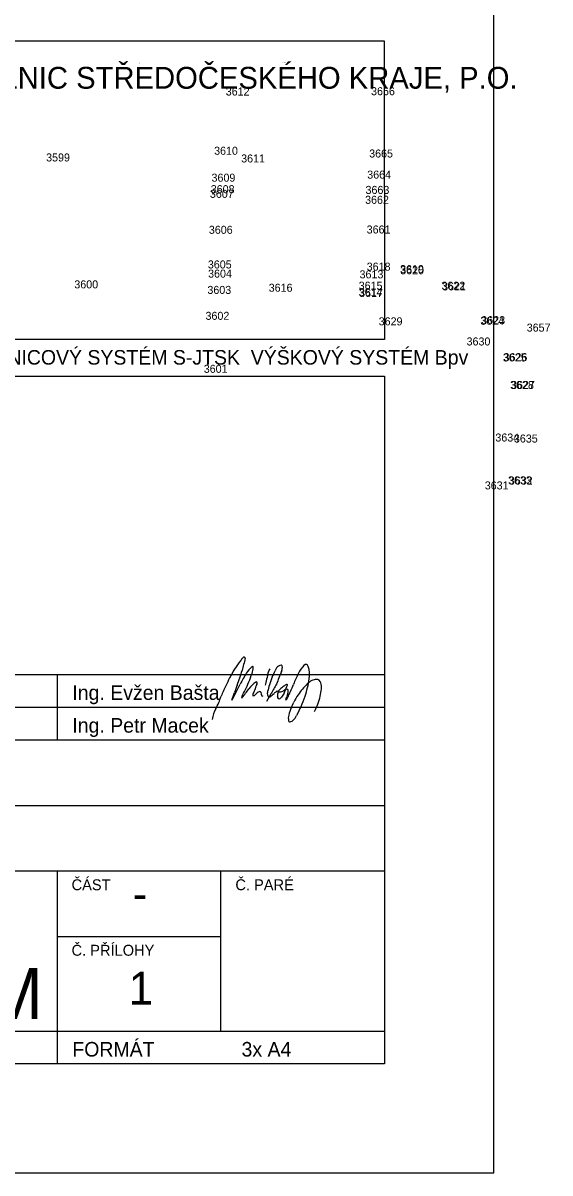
# Model space of a CAD drawing. Extents: x -740053 to -737517, y -1033516 to -1032476.
# Drawn here: x -739026.2 to -738990, y -1032630.6 to -1032551.6 of the extents above; entities that cross this region are included whole.
import ezdxf

# ---------------------------------------------------------------- set-up
doc = ezdxf.new("R2010")
doc.units = 0
for name, color, linetype in [('_MIKA', 7, 'Continuous'), ('bod-cislo', 7, 'Continuous'), ('bod-oznac', 7, 'Continuous'), ('bod-vyska100', 7, 'Continuous'), ('promika-formát', 7, 'Continuous'), ('promika-rozp', 7, 'Continuous'), ('promika-rozp-text-firmy', 7, 'Continuous')]:
    doc.layers.add(name, color=color, linetype=linetype)

# ---------------------------------------------------------------- blocks, each defined once
blk = doc.blocks.new('POINT_DISPLAY')
blk.add_line((0, 0), (0, 0))

msp = doc.modelspace()

# ---------------------------------------------------------------- linework, layer by layer
at = {"layer": '_MIKA'}
msp.add_lwpolyline([(-739009.476, -1032598.222), (-739009.188, -1032597.697)], dxfattribs=at)
for centre, radius, start, end in [((-739005.594, -1032599.849), 7.198, 142.23523, 153.41785), ((-738992.887, -1032609.693), 23.272, 141.62525, 142.23523), ((-738996.81, -1032599.261), 14.699, 164.31686, 167.58851), ((-739011.038, -1032595.32), 0.119, 77.65258, 141.62525), ((-739011.027, -1032595.27), 0.068, 344.31686, 77.65258), ((-739053.316, -1032582.132), 44.406, 340.28609, 341.66347), ((-739005.179, -1032599.978), 6.785, 146.97351, 154.45028), ((-739020.269, -1032592.912), 10.355, 333.90134, 340.8079), ((-739009.171, -1032597.384), 2.025, 132.28695, 146.97351), ((-739010.453, -1032595.953), 0.104, 95.68301, 139.83775), ((-739011.889, -1032595.826), 1.483, 340.68391, 357.12395), ((-739010.452, -1032595.892), 0.0444, 349.81416, 105.49835), ((-739010.138, -1032596.167), 0.767, 337.07897, 353.18058), ((-739008.911, -1032596.313), 0.468, 139.22083, 173.18058), ((-739013.245, -1032594.388), 4.673, 332.41674, 338.14258), ((-739008.101, -1032596.451), 0.869, 143.70851, 158.14258), ((-738853.15, -1032658.556), 167.377, 158.12382, 158.43787), ((-739008.419, -1032596.217), 0.474, 99.82381, 143.70851), ((-739008.537, -1032595.875), 0.13, 357.13165, 73.63723), ((-739009.365, -1032595.834), 0.96, 338.12382, 357.13165), ((-739001.446, -1032599.381), 6.616, 152.29875, 159.50378), ((-739004.761, -1032597.641), 2.872, 139.05622, 152.29875), ((-739006.8, -1032595.872), 0.173, 15.21404, 139.05622), ((-739008.446, -1032596.403), 1.902, 351.39073, 17.62988), ((-738926.054, -1032639.648), 96.139, 153.41785, 153.77616), ((-739027.937, -1032589.099), 18.439, 330.61841, 334.45028), ((-738990.516, -1032604.635), 22.304, 160.28609, 161.69166), ((-739009.162, -1032598.454), 1.885, 124.89597, 145.05699), ((-739004.859, -1032599.225), 5.731, 157.76834, 162.23546), ((-739010.196, -1032596.972), 0.0779, 55.10403, 124.89597), ((-739010.395, -1032596.962), 0.25, 337.76834, 12.42518), ((-739006.502, -1032597.698), 3.146, 165.90811, 169.54357), ((-738990.1, -1032601.816), 20.058, 164.53011, 165.90811), ((-738995.104, -1032601.534), 14.867, 162.64406, 164.43328), ((-739000.908, -1032599.72), 8.786, 158.86527, 162.64406), ((-738990.399, -1032608.008), 21.433, 149.22929, 151.24035), ((-739007.055, -1032598.93), 2.144, 119.74147, 125.81479), ((-739008.098, -1032597.105), 0.0415, 339.1031, 119.74147), ((-739013.783, -1032594.934), 6.128, 338.12374, 339.1031), ((-739014.076, -1032594.66), 6.867, 335.01458, 339.50378), ((-739002.155, -1032601.506), 6.376, 135.47239, 144.29948), ((-739014.179, -1032595.535), 7.701, 342.2433, 351.39073), ((-739005.897, -1032597.826), 1.128, 115.27288, 135.47239), ((-739006.032, -1032597.54), 0.811, 93.24087, 115.27288), ((-739006.06, -1032597.039), 0.309, 16.61177, 93.24087), ((-739006.748, -1032597.244), 1.026, 352.45357, 16.61177), ((-739021.984, -1032594.371), 10.012, 334.10342, 339.46538), ((-739005.242, -1032600.642), 7.866, 153.77616, 159.46538), ((-739032.867, -1032590.622), 22.304, 340.28609, 341.69166), ((-739010.943, -1032597.989), 0.266, 150.33743, 175.43081), ((-739016.415, -1032594.872), 6.032, 330.33743, 334.51836), ((-739018.32, -1032592.055), 9.287, 320.38725, 325.05699), ((-739010.303, -1032597.777), 0.143, 157.34282, 210.29061), ((-739008.128, -1032598.685), 2.501, 151.08165, 157.34281), ((-739010.446, -1032597.584), 0.266, 274.06523, 322.04071), ((-739009.824, -1032598.069), 0.522, 109.96924, 142.04071), ((-739009.953, -1032597.661), 0.0966, 16.46783, 120.57707), ((-739011.327, -1032597.902), 1.491, 4.64701, 10.37671), ((-739009.75, -1032597.783), 0.0917, 178.87234, 265.72159), ((-739008.94, -1032597.679), 0.503, 164.43328, 200.27708), ((-739009.305, -1032597.814), 0.115, 200.27708, 295.62005), ((-739010.747, -1032595.807), 2.584, 305.25171, 313.28111), ((-739008.17, -1032598.543), 1.174, 123.9927, 133.28111), ((-739008.769, -1032597.617), 0.0751, 330.79764, 140.06184), ((-739008.568, -1032597.918), 0.174, 168.44211, 226.63633), ((-739010.818, -1032597.458), 2.124, 348.4421, 354.69045), ((-739008.628, -1032597.534), 0.0443, 160.07678, 271.04324), ((-739008.549, -1032597.562), 0.128, 132.49991, 160.07678), ((-739013.046, -1032592.655), 6.527, 312.49991, 313.21132), ((-739008.648, -1032596.454), 1.123, 271.04324, 277.1213), ((-739006.737, -1032599.37), 2.686, 125.81479, 133.21132), ((-739008.558, -1032597.172), 0.4, 277.1213, 296.25137), ((-738834.069, -1032708.825), 206.658, 147.46165, 147.55364), ((-739008.598, -1032597.092), 0.489, 296.25137, 309.92826), ((-739021.868, -1032591.688), 14.839, 336.22301, 338.12374), ((-739008.055, -1032597.741), 0.357, 114.58049, 129.92826), ((-739008.125, -1032597.588), 0.188, 88.02122, 114.58049), ((-739009.201, -1032597.308), 1.33, 321.43729, 335.0016), ((-739009.294, -1032597.626), 1.216, 341.13101, 346.95348), ((-739008.126, -1032597.61), 0.211, 61.49258, 88.02122), ((-739007.434, -1032598.057), 0.693, 155.07666, 166.95348), ((-739008.627, -1032597.502), 0.622, 335.07666, 354.59191), ((-739008.321, -1032597.531), 0.315, 354.59191, 19.66909), ((-740374.35, -1031960.775), 1507.586, 335.001598, 335.014577), ((-739005.051, -1032599.426), 2.811, 144.29948, 156.17031), ((-739011.741, -1032596.315), 5.141, 333.88055, 342.2433), ((-739009.231, -1032597.185), 3.487, 330.20089, 348.45026), ((-739012.991, -1032596.417), 7.325, 348.45026, 352.45357), ((-739011.186, -1032597.97), 0.0218, 175.43081, 341.96748), ((-739008.644, -1032597.838), 0.211, 258.27689, 327.55364), ((-739006.993, -1032598.412), 1.216, 161.13101, 166.95348), ((-739008.169, -1032598.139), 0.00871, 166.95348, 13.04652), ((-739005.795, -1032599.657), 2.232, 154.16547, 167.44743), ((-739018.982, -1032593.273), 12.418, 334.16547, 336.17031), ((-735753.293, -1034193.984), 3623.913, 153.880552, 153.891528), ((-739011.307, -1032599.704), 1.927, 150.11086, 172.99111), ((-739007.11, -1032599.395), 0.892, 165.54134, 191.72704), ((-739008.401, -1032598.726), 1.081, 312.0858, 333.89153), ((-739007.88, -1032599.529), 0.114, 204.62312, 301.34548), ((-739008.095, -1032599.066), 0.623, 296.02507, 312.0858)]:
    msp.add_arc(centre, radius, start, end, dxfattribs=at)
at = {"layer": 'promika-formát'}
msp.add_lwpolyline([(-739098.885, -1032630.632), (-738993.885, -1032630.632), (-738993.885, -1032482.132), (-739098.885, -1032482.132)], close=True, dxfattribs=at)
at = {"layer": 'promika-rozp'}
for p, q in [((-739091.385, -1032596.382), (-739001.385, -1032596.382)), ((-739023.885, -1032596.382), (-739023.885, -1032600.882)), ((-739091.385, -1032598.632), (-739001.385, -1032598.632)), ((-739091.385, -1032600.882), (-739001.385, -1032600.882)), ((-739091.385, -1032605.382), (-739001.385, -1032605.382)), ((-739091.385, -1032609.882), (-739001.385, -1032609.882)), ((-739023.885, -1032609.882), (-739023.885, -1032623.132)), ((-739012.635, -1032620.882), (-739012.635, -1032609.882)), ((-739023.885, -1032614.382), (-739012.635, -1032614.382)), ((-739091.385, -1032620.882), (-739001.385, -1032620.882))]:
    msp.add_line(p, q, dxfattribs=at)
for points in [[(-739001.385, -1032563.132), (-739001.385, -1032552.882), (-739091.385, -1032552.882), (-739091.385, -1032563.132)], [(-739001.385, -1032563.132), (-739001.385, -1032573.382), (-739091.385, -1032573.382), (-739091.385, -1032563.132)], [(-739091.385, -1032596.382), (-739091.385, -1032575.882), (-739001.385, -1032575.882), (-739001.385, -1032596.382)], [(-739001.385, -1032596.382), (-739001.385, -1032623.132), (-739091.385, -1032623.132), (-739091.385, -1032596.382)], [(-739091.385, -1032600.882), (-739001.385, -1032600.882)]]:
    msp.add_lwpolyline(points, dxfattribs=at)

# ---------------------------------------------------------------- block references
at = {"layer": 'bod-oznac'}
for p in [(-739018.232, -1032554.367), (-739008.252, -1032554.347)]:
    msp.add_blockref('POINT_DISPLAY', p, dxfattribs=at)

# ---------------------------------------------------------------- texts
at = {"layer": 'bod-cislo'}
for s, p in [('3612', (-739012.298, -1032556.613)), ('3666', (-739002.318, -1032556.593)), ('3599', (-739024.635, -1032561.143)), ('3610', (-739013.098, -1032560.683)), ('3611', (-739011.239, -1032561.213)), ('3665', (-739002.448, -1032560.873)), ('3609', (-739013.275, -1032562.533)), ('3664', (-739002.581, -1032562.323)), ('3607', (-739013.388, -1032563.643)), ('3608', (-739013.328, -1032563.323)), ('3663', (-739002.698, -1032563.373)), ('3662', (-739002.728, -1032564.053)), ('3661', (-739002.619, -1032566.093)), ('3606', (-739013.458, -1032566.113)), ('3605', (-739013.528, -1032568.493)), ('3604', (-739013.511, -1032569.123)), ('3613', (-739003.108, -1032569.173)), ('3618', (-739002.618, -1032568.643)), ('3619', (-739000.325, -1032568.813)), ('3620', (-739000.318, -1032568.893)), ('3600', (-739022.698, -1032569.863)), ('3615', (-739003.168, -1032569.953)), ('3622', (-738997.488, -1032569.953)), ('3621', (-738997.439, -1032570.003)), ('3603', (-739013.558, -1032570.243)), ('3616', (-739009.348, -1032570.093)), ('3614', (-739003.171, -1032570.393)), ('3617', (-739003.138, -1032570.453)), ('3602', (-739013.688, -1032572.023)), ('3629', (-739001.795, -1032572.403)), ('3624', (-738994.811, -1032572.363)), ('3623', (-738994.748, -1032572.323)), ('3657', (-738991.628, -1032572.833)), ('3630', (-738995.758, -1032573.783)), ('3625', (-738993.268, -1032574.883)), ('3626', (-738993.218, -1032574.863)), ('3601', (-739013.809, -1032575.663)), ('3628', (-738992.768, -1032576.773)), ('3627', (-738992.708, -1032576.773)), ('3634', (-738993.781, -1032580.383)), ('3635', (-738992.508, -1032580.453)), ('3633', (-738992.908, -1032583.323)), ('3632', (-738992.858, -1032583.343)), ('3631', (-738994.509, -1032583.673))]:
    msp.add_text(s, height=0.55, dxfattribs=at).set_placement(p)
at = {"layer": 'bod-vyska100'}
for s, p in [('297 95', (-739018.399, -1032554.4)), ('297 60', (-739008.42, -1032554.38))]:
    msp.add_text(s, height=0.05, dxfattribs=at).set_placement(p)
at = {"layer": 'promika-rozp'}
for s, height, p in [('SOUŘADNICOVÝ SYSTÉM S-JTSK  VÝŠKOVÝ SYSTÉM Bpv', 1, (-739033.017, -1032575.1)), ('Ing. Evžen Bašta', 1, (-739022.833, -1032598.132)), ('Ing. Petr Macek', 1, (-739022.833, -1032600.382)), ('ČÁST', 0.75, (-739022.886, -1032611.207)), ('Č. PARÉ', 0.75, (-739011.636, -1032611.207)), ('-', 2.25, (-739018.678, -1032612.56)), ('Č. PŘÍLOHY', 0.75, (-739022.886, -1032615.707)), ('1', 2.25, (-739018.959, -1032619.06)), ('FORMÁT', 1, (-739022.833, -1032622.632)), (' 3x A4', 1, (-739011.583, -1032622.632))]:
    msp.add_text(s, height=height, dxfattribs=at).set_placement(p)
at = {"layer": 'promika-rozp-text-firmy'}
for s, height, p in [('KRAJSKÁ SPRÁVA A ÚDRŽBA SILNIC STŘEDOČESKÉHO KRAJE, P.O.', 1.5, (-739058.689, -1032556.147)), ('DENDROLOGICKÝ PRŮZKUM', 3.5, (-739090.386, -1032620.05))]:
    msp.add_text(s, height=height, dxfattribs=at).set_placement(p)

doc.saveas('drawing.dxf')
